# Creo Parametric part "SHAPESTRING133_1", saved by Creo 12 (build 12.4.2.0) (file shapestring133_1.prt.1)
Units: Custom; MM, KILOGRAM, SECS

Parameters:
  PTC_WM_ITERATION = "0"
  PTC_WM_VERSION = "-.0"
  PTC_WM_LIFECYCLE_STATE = "In Work"
  PTC_WM_LIFECYCLE = "MO_CADDocument"
  PTC_WM_CREATED_BY = "Maximilian Roepper (Z0017RMS: MO)"
  PTC_WM_CREATED_ON = "18-Sep-26 11:36:42 AM"
  PTC_WM_MODIFIED_BY = "Maximilian Roepper (Z0017RMS: MO)"
  PTC_WM_MODIFIED_ON = "18-Sep-26 11:36:46 AM"
  PDMLINKNUMBER = "PDM000071454914"
  PTC_WM_NAME = "shapestring133_1.prt"
  PTC_WM_NUMBER = "PDM000071454914"

Other parameters: WEIGHT, WEIGHT_FACTOR, WEIGHT_ADD, _MASS_TEMP, _DIFF_TEMP, MC_ERRORS, SUPPLIER

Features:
  1. coordinate system
  2. datum plane "PRT_YZ"
  3. datum plane "PRT_XY"
  4. datum plane "PRT_XZ"
  5. coordinate system
  6. datum axis
  7. datum axis
  8. datum axis
  9. coordinate system
  10. imported feature
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
Other named items: PRT, SIEMENS_MO, DRW_VIEW_ORG, PRT_X, PRT_Y, PRT_Z, CS0, ROUGH_GROB

Layers: 00_STD_CSYS-KSYS, 01_STD_PLANES-EBENEN, 02_STD_AXES-ACHSEN, 03_STD_CSYS-KSYS, 24_IMPORT_FEAT-IMPORT_KE, INTFCLR

Surfaces: 1 plane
